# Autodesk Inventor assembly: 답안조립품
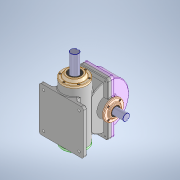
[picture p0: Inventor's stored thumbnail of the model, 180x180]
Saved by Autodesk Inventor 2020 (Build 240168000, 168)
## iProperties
Created: 2023-07
Part Number: 답안조립품
Document SubType Name: Assembly
Designer: oem
Author: oem
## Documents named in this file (14)
- C:\Users\oem\Desktop\730706V1012\답안조립품.iam
- C:\Users\oem\Desktop\730706V1012\본체.ipt
- C:\Users\oem\Desktop\730706V1012\깊은 홈 볼 베어링 6209.ipt
- C:\Users\oem\Desktop\730706V1012\앞커버.ipt
- C:\Users\oem\Desktop\730706V1012\웜 샤프트.ipt
- C:\Users\oem\Desktop\730706V1012\뒤커버.ipt
- C:\Users\oem\Desktop\730706V1012\육각 소켓 머리 볼트 M5 x 12.ipt
- C:\Users\oem\Desktop\730706V1012\오일 실 35 55 11.ipt
- C:\Users\oem\Desktop\730706V1012\깊은 홈 볼 베어링 6206.ipt
- C:\Users\oem\Desktop\730706V1012\웜 휠.ipt
- C:\Users\oem\Desktop\730706V1012\본체 커버.ipt
- C:\Users\oem\Desktop\730706V1012\육각 소켓 머리 볼트 M6 x 20.ipt
- C:\Users\oem\Desktop\730706V1012\서브커버.ipt
- C:\Users\oem\Desktop\730706V1012\오일 실 30 42 7.ipt
